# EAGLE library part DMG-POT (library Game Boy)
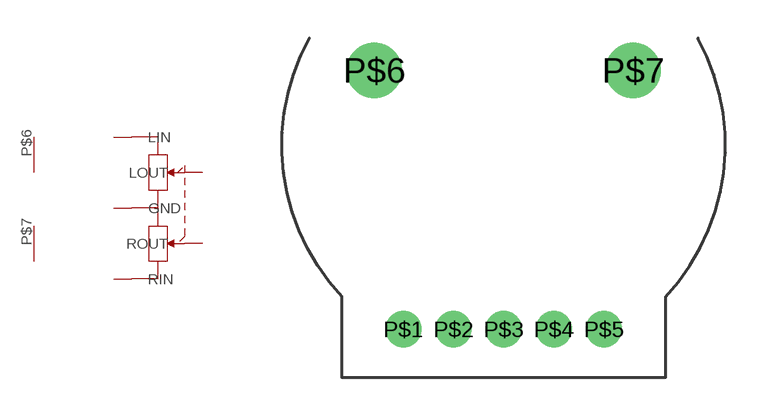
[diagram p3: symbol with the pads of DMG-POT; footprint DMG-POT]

Designator prefix -; gates G$1=DMG-POT G$2=PWRGND G$3=PWRGND

## DMG-POT  [DMG-POT]
P$1  G$1:GND
P$2  G$1:ROUT
P$3  G$1:LOUT
P$4  G$1:LIN
P$5  G$1:RIN
P$6  G$2:GND  pwr
P$7  G$3:GND  pwr

## Footprint DMG-POT (pad centres in mm)
drill 0.8 pad 1.422 round: P$1 -3.937,-5.08; P$2 -1.968,-5.08; P$3 0,-5.08; P$4 1.968,-5.08; P$5 3.937,-5.08
drill 1.1 pad 2.184 round: P$6 -5.08,5.08; P$7 5.08,5.08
